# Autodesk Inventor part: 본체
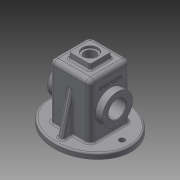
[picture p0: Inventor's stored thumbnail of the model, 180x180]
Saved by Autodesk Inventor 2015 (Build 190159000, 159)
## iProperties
Created: 2017-07
Part Number: 본체
Material: 일반
Document SubType Name: Modeling
Designer: Administrator
Density: 1 g/cm^3
Appearance: 기본값
Author: Administrator
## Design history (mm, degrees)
sketch "스케치1" dims "d0" = 75, "d1" = 65
  geometry: 2 further points; 1 other entity
  constraints: 1 coincident, 2 other
extrude "돌출1" new body sketch "스케치1" distance "d2" = 10; taper "d3" = 0 deg
sketch "스케치2"
  geometry: L1 (-37, 37)-(37, 37); L2 (37, 37)-(37, -37); L3 (37, -37)-(-37, -37); L4 (-37, -37)-(-37, 37); L5 (-37, 37)-(37, -37); 2 further points
  constraints: 10 end point, 2 parallel, 1 coincident, 1 horizontal, 1 midpoint, 1 perpendicular
  dimensions: "d4" = 74 distance of L1.start L1.end; "d5" = 74 distance of L3.end L1.start
extrude "돌출2" join sketch "스케치2" distance "d6" = 100; taper "d7" = 0 deg
sketch "스케치3"
  geometry: L1 (-37, -37)-(37, -37) reference; L2 (-37, 37)-(-37, -37) reference; L3 (37, -37)-(37, 37) reference; L4 (37, 37)-(-37, 37) reference; L5 (32, -32)-(-32, -32); L6 (-32, -32)-(-32, 32); L7 (-32, 32)-(32, 32); L8 (32, 32)-(32, -32); 1 further point
  constraints: 8 end point, 3 other
  dimensions: "d8" = 5 distance between parallel lines of L1 L5
extrude "돌출3" cut sketch "스케치3" distance "d9" = 105; taper "d10" = 0 deg
sketch "스케치4"
  geometry: L1 (67.009, 55)-(-78.153, 55); L2 (-75, 0)-(75, 0) reference; L3 (32, 0)-(32, 105) reference; L4 (32, 82.5)-(25, 75.5); L5 (25, 75.5)-(25, 55); L6 (32, 55)-(25, 55); L7 (32, 82.5)-(32, 55); 1 further point
  constraints: 10 end point, 4 point on line, 1 collinear, 1 horizontal, 1 perpendicular, 1 vertical
  dimensions: "d11" = 55 distance between parallel lines of L1 L2; "d12" = 55 diameter of L4.start L1; "d13" = 7 distance between parallel lines of L5 L3; "d14" = 135 deg angle of L3 L4
revolve "회전1" sketch "스케치4" stored, may be unused: angle "d15" = 90 deg
sketch "스케치5"
  geometry: L1 (-10, 102)-(-10, -28) reference; L2 (-10, 37)-(99.532, 37); C1 r 27.5 at (45, 37)
  constraints: 2 end point, 1 centre point, 1 horizontal
  dimensions: "d16" = 55 diameter of C1; "d17" = 55 distance from line of L1 C1.centre
extrude "돌출4" join sketch "스케치5" distance "d18" = 13; taper "d19" = 0 deg
hole "구멍1" diameter "d22" = 32; stored, may be unused: countersink angle "d26" = 90 deg, drill point angle "d28" = 118 deg; dims "d20" = 10, "d21" = 10, "d23" = 6, "d24" = 4, "d25" = 2, "d27" = 8
chamfer "모따기1" distance "d29" = 1; stored, may be unused: second distance "d30" = 2, angle "d31" = 45 deg
sketch "스케치6"
  geometry: L1 (37, 37)-(-37, 37) reference; L2 (-37, 37)-(-37, -37) reference; L3 (-37, -37)-(37, -37) reference; L4 (37, -37)-(37, 37) reference; L5 (-20, 20)-(20, 20); L6 (20, 20)-(20, -20); L7 (20, -20)-(-20, -20); L8 (-20, -20)-(-20, 20); L9 (-20, 20)-(20, -20); 2 further points
  constraints: 10 end point, 2 parallel, 1 coincident, 1 horizontal, 1 midpoint, 1 perpendicular
  dimensions: "d32" = 40 distance of L5.start L5.end; "d33" = 40 distance of L7.end L5.start
extrude "돌출5" join sketch "스케치6" distance "d34" = 10; taper "d35" = -5 deg
sketch "스케치8"
  geometry: C1 r 14 at (0, 0); 1 further point
  constraints: 1 centre point, 1 coincident
  dimensions: "d36" = 28 diameter of C1
extrude "돌출6" cut sketch "스케치8" distance "d37" = 4; taper "d38" = 0 deg
hole "구멍2" diameter "d41" = 21; stored, may be unused: countersink angle "d45" = 90 deg, drill point angle "d47" = 118 deg; dims "d39" = 10, "d40" = 10, "d42" = 6, "d43" = 4, "d44" = 2, "d46" = 8
fillet "모깎기1" dims "d48" = 8
fillet "모깎기2" dims "d49" = 8
sketch "스케치10"
  geometry: L1 (65, 10)-(-65, 10) reference; L2 (-65, 0)-(65, 0) reference; L3 (-37, 102)-(-37, 10) reference; L4 (-55, 10)-(-37, 82.194); 1 further point
  constraints: 2 end point, 2 point on line
  dimensions: "d50" = 76 deg angle of L4 L1; "d51" = 10 distance of L1.end L4.start
feature "리브1" sketch "스케치10" dims "d52" = 1, "d53" = 10, "d54" = 0, "d55" = 0, "d56" = 1, "d57" = 1
fillet "모깎기3" dims "d58" = 3
fillet "모깎기4" dims "d59" = 3
fillet "모깎기5" dims "d60" = 3
fillet "모깎기6" dims "d61" = 3
sketch "스케치11"
  geometry: 1 further point
fillet "모깎기7" dims "d62" = 3
fillet "모깎기8" dims "d63" = 3
fillet "모깎기9" dims "d64" = 3
sketch "스케치12" dims "d65" = 45
  geometry: C1 r 27.5 at (0, 0) reference; C2 r 17 at (0, 0) reference; 3 further points
  constraints: 1 coincident, 1 horizontal alignment, 2 other
hole "구멍3" sketch "스케치12" at (-22.5, 0) diameter "d66" = 3.459; stored, may be unused: countersink angle "d70" = 90 deg, drill point angle "d72" = 118 deg; dims "d67" = 8, "d68" = 4, "d69" = 2, "d71" = 10
fillet "모깎기10" dims "d76" = 0.5
fillet "모깎기11" dims "d77" = 0.5
sketch "스케치13"
  geometry: L1 (0, 0)-(-58, 0); C1 r 5 at (-58, 0)
  constraints: 2 end point, 1 centre point, 1 coincident, 1 horizontal
  dimensions: "d78" = 58 distance of L1.start L1.end; "d79" = 10 diameter of C1
extrude "돌출7" cut sketch "스케치13" stored distance "d80" = 4; taper "d81" = 0 deg
sketch "스케치14"
  geometry: L1 (9.186, 9.113)-(9.186, 48.887); L2 (9.186, 48.887)-(14.814, 48.887); L3 (14.814, 48.887)-(14.814, 9.113); L4 (14.814, 9.113)-(9.186, 9.113); L5 (9.186, 9.113)-(14.814, 48.887); L6 (102, 29)-(-34.324, 29); L7 (-18, 45.137)-(-18, 12.863) reference; 1 further point
  constraints: 4 end point, 1 horizontal, 1 midpoint, 1 point on line, 2 other
  dimensions: "d82" = 30 distance from line of point (12, 29) L7
feature "엠보싱1" sketch "스케치14" dims "d0" = 75, "d8" = 5, "d83" = 0.5, "d84" = 0
node "솔리드1"
mirror "대칭1"
mirror "대칭2"
mirror "대칭3"
pattern_circular "원형 패턴1" dims angle "d74" = 360 deg
mirror "대칭4"
mirror "대칭5"
node "투영된 루프1"
node "투영된 루프2"
node "투영된 루프3"
